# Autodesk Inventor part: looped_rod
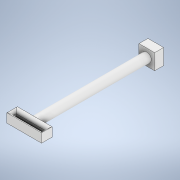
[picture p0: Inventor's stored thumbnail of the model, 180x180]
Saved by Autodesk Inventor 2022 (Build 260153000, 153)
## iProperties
Created: 2021-06
Part Number: looped_rod
Material: PC/ABS Plastic
Document SubType Name: Modeling
Designer: Chimms
Density: 0.357273 g/cm^3
Appearance: Smooth - White
Author: Chimms
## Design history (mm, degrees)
sketch "Sketch1"
  geometry: C1 r 2 at (0, 0); 1 further point
  constraints: 1 centre point, 1 coincident
  dimensions: "d0" = 4 diameter of C1
extrude "Extrusion1" new body sketch "Sketch1" distance "d1" = 50; taper "d2" = 0 deg
sketch "Sketch2"
  geometry: L1 (0, 0)-(6.75, 0); L2 (6.75, 0)-(6.75, 2); L3 (6.75, 2)-(0, 2); L4 (0, 2)-(-6.75, 2); L5 (-6.75, 2)-(-6.75, 0); L6 (-6.75, 0)-(-6.75, -2); L7 (-6.75, -2)-(0, -2); L8 (0, -2)-(6.75, -2); L9 (6.75, 0)-(6.75, -2); A1 r 2 centre (0, 0) between (0, 2) and (0, -2) reference
  constraints: 18 end point, 4 point on line, 3 perpendicular, 1 horizontal, 1 point on circle, 1 tangent, 1 vertical
  dimensions: "d3" = 6.75 distance of L1.start L1.end; "d4" = 2 distance of L1.end L2.end; "d5" = 6.75 distance of L3.end L4.end
extrude "Extrusion2" join sketch "Sketch2" distance "d6" = 1.5; taper "d7" = 0 deg
sketch "Sketch3"
  geometry: L1 (6.75, -2)-(6.75, 2) reference; L2 (6.75, 2)-(7.75, 2); L3 (7.75, 2)-(7.75, -2); L4 (7.75, -2)-(6.75, -2); L5 (6.75, -2)-(6.75, 2); 2 further points
  constraints: 8 end point, 2 parallel, 1 horizontal, 1 perpendicular
  dimensions: "d8" = 1 distance of L3.end L4.end
extrude "Extrusion3" join sketch "Sketch3" distance "d9" = 1.5; taper "d10" = 0 deg
sketch "Sketch4"
  geometry: L1 (-6.75, 2)-(-6.75, -2) reference; L2 (-6.75, 2)-(-7.75, 2); L3 (-7.75, 2)-(-7.75, -2); L4 (-7.75, -2)-(-6.75, -2); L5 (-6.75, -2)-(-6.75, 2); 2 further points
  constraints: 8 end point, 2 parallel, 1 horizontal, 1 perpendicular
  dimensions: "d11" = 1 distance of L4.end L3.end
extrude "Extrusion4" join sketch "Sketch4" distance "d12" = 1.5; taper "d13" = 0 deg
sketch "Sketch5"
  geometry: L1 (7.75, 2)-(-7.75, 2) reference; L2 (7.75, 2)-(6.75, 2); L3 (6.75, 2)-(6.75, -2); L4 (6.75, -2)-(7.75, -2); L5 (7.75, -2)-(7.75, 2); L6 (-7.75, -2)-(-7.75, 2) reference; L7 (-7.75, -2)-(7.75, -2) reference; L8 (-7.75, 2)-(-6.75, 2); L9 (-6.75, 2)-(-6.75, -2); L10 (-6.75, -2)-(-7.75, -2); L11 (-7.75, -2)-(-7.75, 2); 3 further points
  constraints: 16 end point, 4 parallel, 2 horizontal, 2 perpendicular, 1 point on line
  dimensions: "d14" = 1 distance of L4.end L3.end; "d15" = 1 distance of L9.end L10.end
extrude "Extrusion5" join sketch "Sketch5" distance "d16" = 2.2; taper "d17" = 0 deg
sketch "Sketch6"
  geometry: L1 (0, 2)-(-7.75, 2) reference; L2 (-6.75, 2)-(-6.75, -2) reference; L3 (-7.75, 2)-(-6.75, 2); L4 (-6.75, 2)-(-6.75, -2); L5 (-6.75, -2)-(-7.75, -2); L6 (-7.75, -2)-(-7.75, 2); L7 (7.75, 2)-(7.75, -2) reference; L8 (0, 2)-(7.75, 2) reference; L9 (7.75, -2)-(6.75, -2); L10 (6.75, -2)-(6.75, 2); L11 (6.75, 2)-(7.75, 2); L12 (7.75, 2)-(7.75, -2); 1 further point
  constraints: 16 end point, 4 parallel, 2 horizontal, 2 perpendicular, 1 point on line
  dimensions: "d18" = 1 distance of L10.end L11.end
extrude "Extrusion6" join sketch "Sketch6" distance "d19" = 1; taper "d20" = 0 deg
sketch "Sketch7"
  geometry: L1 (0, 4)-(-3.2, 4) reference; L2 (0, 0)-(-3.2, 0) reference; L3 (-3.2, 4)-(-2, 4); L4 (-2, 4)-(-2, 0); L5 (-2, 0)-(-3.2, 0); L6 (-3.2, 0)-(-3.2, 4); 3 further points
  constraints: 8 end point, 2 parallel, 1 horizontal, 1 perpendicular, 1 point on line
  dimensions: "d21" = 1.2 distance of L4.end L5.end
extrude "Extrusion7" join sketch "Sketch7" distance "d22" = 13.5; taper "d23" = 0 deg
fillet "Fillet1" dims "d24" = 1.5
fillet "Fillet2" dims "d25" = 1.5
fillet "Fillet3" dims "d26" = 1.5
fillet "Fillet4" dims "d27" = 1.5
fillet "Fillet5" dims "d28" = 1.5
sketch "Sketch8"
  geometry: L1 (0, 0)-(-3.5, 0); L2 (-3.5, 0)-(-3.5, 3.5); L3 (-3.5, 3.5)-(0, 3.5); L4 (0, 3.5)-(0, 0); L5 (0, -3.5)-(-3.5, -3.5); L6 (-3.5, -3.5)-(-3.5, 0); L7 (-3.5, 0)-(0, 0); L8 (0, 0)-(0, -3.5); L9 (3.5, 0)-(3.5, -3.5); L10 (3.5, -3.5)-(0, -3.5); L11 (0, -3.5)-(0, 0); L12 (0, 0)-(3.5, 0); L13 (0, 3.5)-(3.5, 3.5); L14 (3.5, 3.5)-(3.5, 0); L15 (3.5, 0)-(0, 0); L16 (0, 0)-(0, 3.5); 4 further points
  constraints: 32 end point, 2 coincident, 2 parallel, 1 horizontal, 1 perpendicular, 31 other
  dimensions: "d29" = 3.5 distance of L2.end L3.end; "d30" = 3.5 distance of L1.end L2.end; "d33" = 360 deg dimension on L1.start L1.end (derived)
extrude "Extrusion8" join sketch "Sketch8" distance "d35" = 4; taper "d36" = 0 deg
body "Solid1"
